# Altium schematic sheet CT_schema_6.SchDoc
size 274 x 160 mm
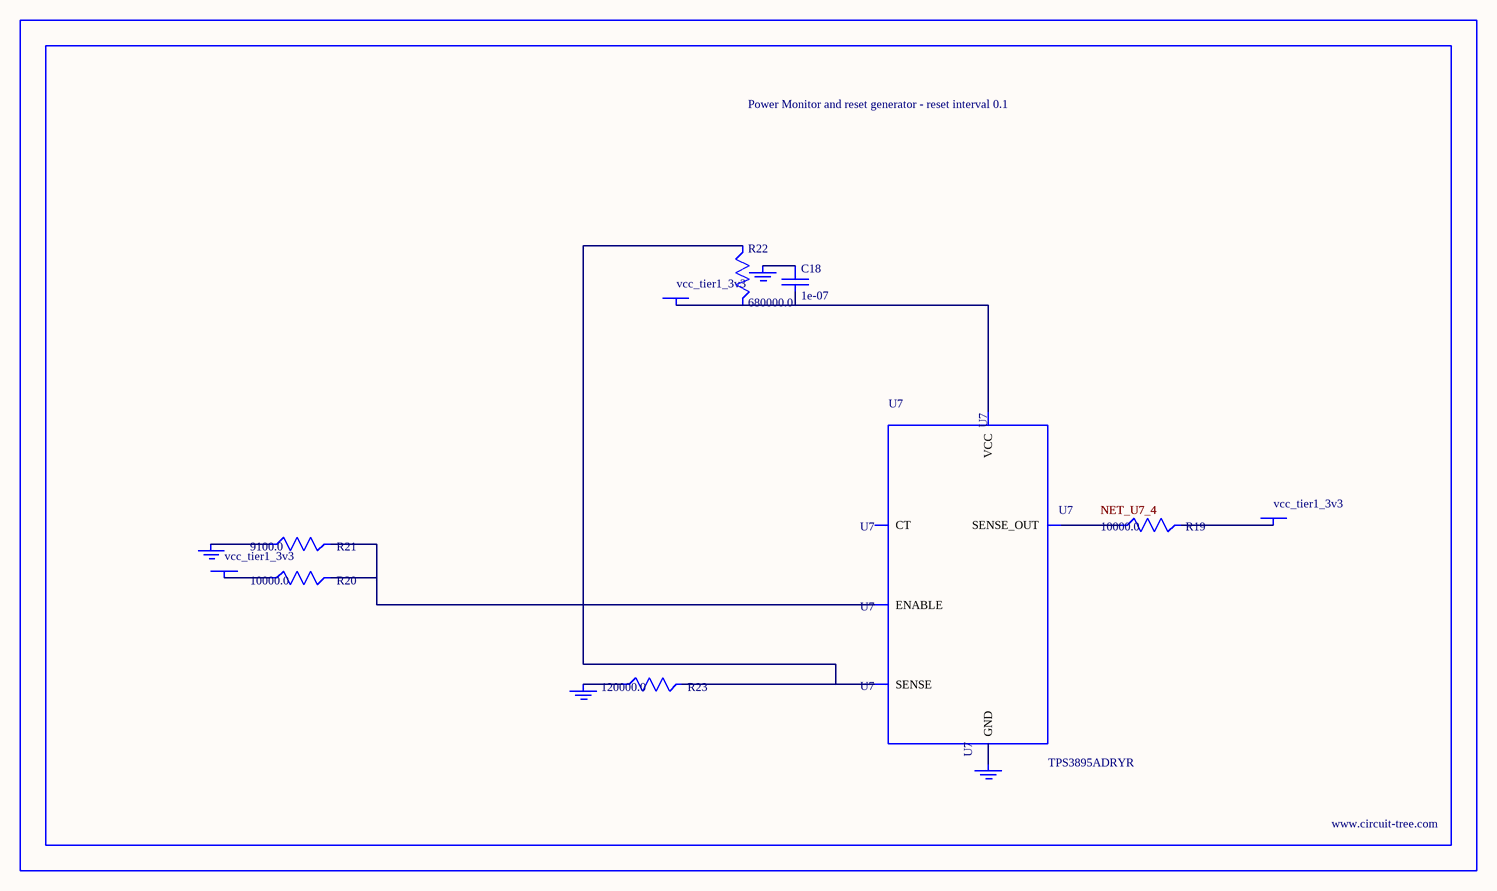
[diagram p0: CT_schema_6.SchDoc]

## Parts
BORDER5  (no value)
C18  1e-07  [C0402]
GND_INSTANCE_5_0  (no value)
GND_INSTANCE_5_1  (no value)
GND_INSTANCE_5_2  (no value)
GND_INSTANCE_5_3  (no value)
POWER_INSTANCE_5_0  vcc_tier1_3v3
POWER_INSTANCE_5_1  vcc_tier1_3v3
POWER_INSTANCE_5_2  vcc_tier1_3v3
R19  10000.0  [R0603]
R20  10000.0  [R0603]
R21  9100.0  [R0603]
R22  680000.0  [R0603]
R23  120000.0  [R0603]
U7  TPS3895ADRYR  [SON-6]

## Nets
NetC18_1: C18.1 GND_INSTANCE_5_2.0(GND)
NetC18_2: C18.2 POWER_INSTANCE_5_2.0(PWR) R22.2 U7.6(VCC)
NetGND_INSTANCE_5_0_0: GND_INSTANCE_5_0.0(GND) R21.1
NetGND_INSTANCE_5_1_0: GND_INSTANCE_5_1.0(GND) R23.1
NetGND_INSTANCE_5_3_0: GND_INSTANCE_5_3.0(GND) U7.2(GND)
NetPOWER_INSTANCE_5_0_0: POWER_INSTANCE_5_0.0(PWR) R20.1
NetPOWER_INSTANCE_5_1_0: POWER_INSTANCE_5_1.0(PWR) R19.2
NetR19_1: R19.1 U7.4(SENSE_OUT)
NetR20_2: R20.2 R21.2 U7.1(ENABLE)
NetR22_1: R22.1 R23.2 U7.3(SENSE)

Not connected (* = marked no-connect by the designer): U7 5(CT)

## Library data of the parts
BORDER5 = BORDER_PAGE5
C18 = C0402C104K3RACTU
GND_INSTANCE_5_0-GND_INSTANCE_5_3 = GND
POWER_INSTANCE_5_0-POWER_INSTANCE_5_2 = PWR
R19 R20 = RC0603JR-0710KL
R21 = RC0603JR-079K1L
R22 = RC0603JR-07680KL
R23 = RC0603JR-07120KL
